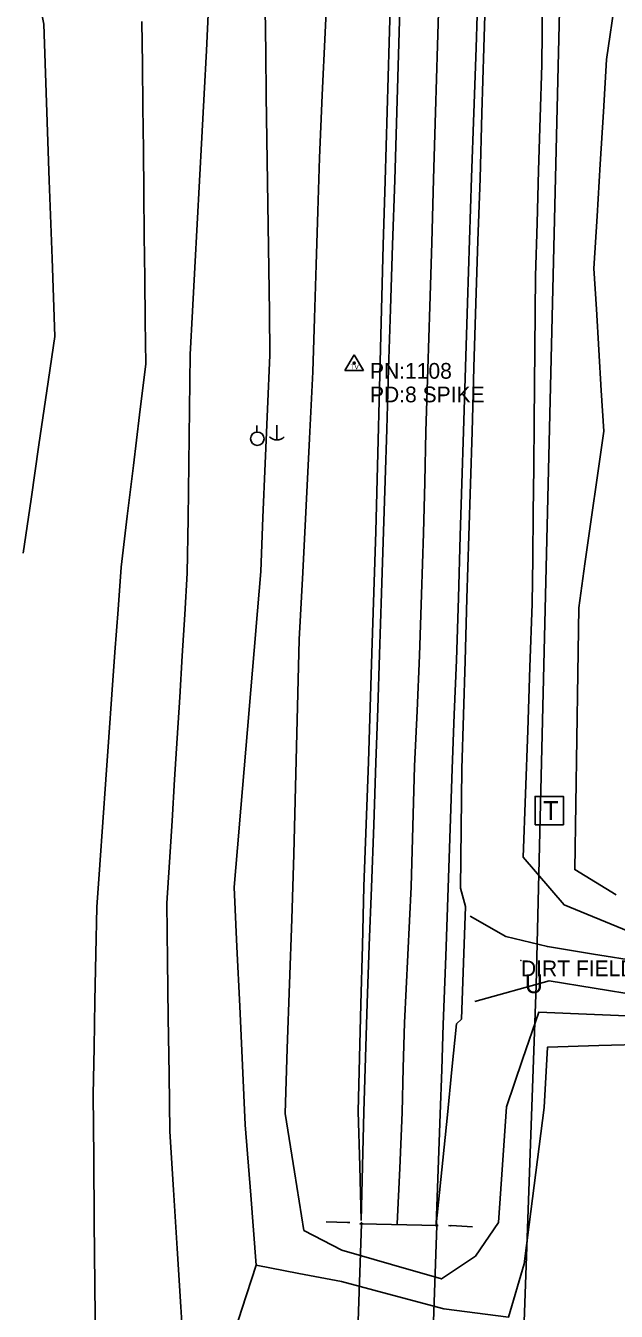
# Model space of a CAD drawing. Extents: x 1445297 to 1476720, y 2042269 to 2057889.
# Drawn here: x 1445978.9 to 1446166.6, y 2044126.9 to 2044535.6 of the extents above; entities that cross this region are included whole.
import ezdxf

# ---------------------------------------------------------------- set-up
doc = ezdxf.new("R2010")
doc.units = 0
for name, color, linetype in [('S_BRIDGE', 7, 'Continuous'), ('S_DITCHLINE', 7, 'Continuous'), ('S_DRIVEWAY', 7, 'Continuous'), ('S_EDGE_PAVEMENT', 7, 'Continuous'), ('S_MSC_PT_SYM', 7, 'Continuous'), ('S_PAVEMENT_CROWN', 7, 'Continuous'), ('S_SECONDARY_CTL', 7, 'Continuous'), ('S_SECONDARY_CTL_ANNOT', 7, 'Continuous'), ('S_SHOULDER', 7, 'Continuous'), ('S_STR_PT_SYM', 7, 'Continuous'), ('S_STREAM', 7, 'Continuous'), ('S_SURVEY_TEXT_ANNOT', 7, 'Continuous'), ('S_TELEPHONE_UTILITIES', 7, 'Continuous'), ('S_UNDERGROUND_CABLE', 7, 'Continuous'), ('S_UTILITY_POLE', 7, 'Continuous'), ('S_UTL_PT_SYM', 7, 'Continuous'), ('S_WALL', 7, 'Continuous')]:
    doc.layers.add(name, color=color, linetype=linetype)

msp = doc.modelspace()

# ---------------------------------------------------------------- linework, layer by layer
at = {"layer": 'S_BRIDGE'}
for p, q in [((1446083.17, 2044079.68), (1446085.63, 2044154.69)), ((1446085.63, 2044154.69), (1446109.56, 2044154.24)), ((1446109.56, 2044154.24), (1446107.11, 2044078.9))]:
    msp.add_line(p, q, dxfattribs=at)
at = {"layer": 'S_DITCHLINE'}
for points in [[(1445978.15, 2044367.9), (1445980.65, 2044385.13), (1445983.14, 2044402.36), (1445985.64, 2044419.58), (1445988.13, 2044436.81), (1445987.28, 2044461.63), (1445986.42, 2044486.45), (1445985.57, 2044511.27), (1445984.71, 2044536.09), (1445981.85, 2044550.56), (1445978.98, 2044565.02), (1445976.11, 2044579.49)], [(1446029.4, 2044109.71), (1446028.22, 2044128.31), (1446027.05, 2044146.91), (1446025.87, 2044165.51), (1446024.69, 2044184.11), (1446024.47, 2044202.24), (1446024.25, 2044220.37), (1446024.03, 2044238.5), (1446023.82, 2044256.64), (1446024.62, 2044269.75), (1446025.43, 2044282.86), (1446026.24, 2044295.98), (1446027.05, 2044309.09), (1446027.86, 2044322.2), (1446028.67, 2044335.32), (1446029.48, 2044348.43), (1446030.29, 2044361.54), (1446030.52, 2044378.93), (1446030.75, 2044396.32), (1446030.98, 2044413.72), (1446031.21, 2044431.11), (1446031.94, 2044444.91), (1446032.68, 2044458.72), (1446033.41, 2044472.52), (1446034.14, 2044486.32), (1446034.87, 2044500.13), (1446035.6, 2044513.93), (1446036.33, 2044527.74), (1446037.06, 2044541.54)], [(1446166.64, 2044259.28), (1446153.45, 2044267.34), (1446153.77, 2044288.14), (1446154.08, 2044308.94), (1446154.4, 2044329.74), (1446154.71, 2044350.54), (1446156.69, 2044364.58), (1446158.67, 2044378.62), (1446160.66, 2044392.66), (1446162.64, 2044406.7), (1446161.86, 2044419.64), (1446161.08, 2044432.58), (1446160.3, 2044445.52), (1446159.52, 2044458.46), (1446160.53, 2044475.06), (1446161.54, 2044491.67), (1446162.55, 2044508.27), (1446163.56, 2044524.88), (1446166.4, 2044544.53)], [(1446043.13, 2044113.76), (1446047.64, 2044127.65), (1446052.16, 2044141.54), (1446050.44, 2044163.85), (1446048.72, 2044186.16), (1446047.84, 2044205.05), (1446046.95, 2044223.94), (1446046.06, 2044242.83), (1446045.17, 2044261.72), (1446046.23, 2044274.27), (1446047.28, 2044286.83), (1446048.33, 2044299.38), (1446049.39, 2044311.93), (1446050.44, 2044324.48), (1446051.49, 2044337.03), (1446052.55, 2044349.58), (1446053.6, 2044362.14), (1446054.34, 2044379.32), (1446055.08, 2044396.5), (1446055.82, 2044413.68), (1446056.56, 2044430.86), (1446056.37, 2044444.61), (1446056.17, 2044458.36), (1446055.97, 2044472.11), (1446055.78, 2044485.86), (1446055.58, 2044499.61), (1446055.39, 2044513.36), (1446055.19, 2044527.11), (1446055, 2044540.86)], [(1446001.05, 2044115.1), (1446000.88, 2044135.29), (1446000.7, 2044155.49), (1446000.53, 2044175.68), (1446000.35, 2044195.87), (1446000.64, 2044210.75), (1446000.93, 2044225.63), (1446001.22, 2044240.52), (1446001.5, 2044255.4), (1446002.47, 2044268.91), (1446003.43, 2044282.43), (1446004.4, 2044295.94), (1446005.36, 2044309.46), (1446006.33, 2044322.98), (1446007.29, 2044336.49), (1446008.26, 2044350.01), (1446009.22, 2044363.52), (1446011.19, 2044379.67), (1446013.16, 2044395.82), (1446015.13, 2044411.97), (1446017.1, 2044428.12), (1446016.94, 2044441.72), (1446016.78, 2044455.33), (1446016.62, 2044468.94), (1446016.47, 2044482.54), (1446016.31, 2044496.15), (1446016.15, 2044509.75), (1446015.99, 2044523.36), (1446015.83, 2044536.97)], [(1446052.16, 2044141.54), (1446065.73, 2044138.95), (1446079.29, 2044136.37), (1446095.55, 2044132.02), (1446111.81, 2044127.68), (1446132.33, 2044125.05), (1446137.31, 2044142.04), (1446138.9, 2044154.47), (1446140.49, 2044166.89), (1446142.09, 2044179.31), (1446143.68, 2044191.74), (1446144.8, 2044210.94), (1446161.07, 2044211.42), (1446177.35, 2044211.9)]]:
    msp.add_lwpolyline(points, dxfattribs=at)
at = {"layer": 'S_DRIVEWAY'}
for points in [[(1446120.2, 2044252.54), (1446131.57, 2044246.1), (1446144.72, 2044242.87), (1446159.4, 2044240.47), (1446174.09, 2044238.08), (1446188.77, 2044235.68), (1446203.45, 2044233.29), (1446218.13, 2044230.89), (1446232.81, 2044228.5), (1446247.49, 2044226.1), (1446262.18, 2044223.71), (1446275.63, 2044222.1), (1446289.08, 2044220.5), (1446302.53, 2044218.89), (1446315.98, 2044217.29), (1446330.69, 2044216.84), (1446345.39, 2044216.38), (1446360.1, 2044215.93), (1446374.81, 2044215.47), (1446389.39, 2044215.28), (1446403.98, 2044215.08), (1446418.56, 2044214.89), (1446433.15, 2044214.69)], [(1446121.63, 2044225.44), (1446145.27, 2044231.95), (1446159.59, 2044229.64), (1446173.9, 2044227.34), (1446188.22, 2044225.04), (1446202.53, 2044222.73), (1446216.85, 2044220.43), (1446231.17, 2044218.12), (1446245.48, 2044215.82), (1446259.8, 2044213.52), (1446273.64, 2044211.76), (1446287.48, 2044209.99), (1446301.32, 2044208.23), (1446315.16, 2044206.47), (1446330.01, 2044206.17), (1446344.87, 2044205.87), (1446359.72, 2044205.56), (1446374.57, 2044205.26), (1446389.23, 2044205.3), (1446403.89, 2044205.33), (1446418.55, 2044205.37), (1446433.2, 2044205.41)]]:
    msp.add_lwpolyline(points, dxfattribs=at)
at = {"layer": 'S_EDGE_PAVEMENT'}
for points in [[(1446085.51, 2044155.74), (1446085.98, 2044173.03), (1446086.44, 2044190.32), (1446086.93, 2044207.59), (1446087.43, 2044224.85), (1446088.13, 2044243.27), (1446088.83, 2044261.7), (1446089.53, 2044281.54), (1446090.23, 2044301.38), (1446090.79, 2044318.55), (1446091.35, 2044335.73), (1446092.01, 2044355.26), (1446092.67, 2044374.79), (1446093.17, 2044391.06), (1446093.67, 2044407.32), (1446094.26, 2044426.43), (1446094.85, 2044445.54), (1446095.53, 2044466.02), (1446096.2, 2044486.51), (1446096.84, 2044508.28), (1446097.48, 2044530.06), (1446098.11, 2044551.51)], [(1446109.42, 2044154.37), (1446110.05, 2044171.97), (1446110.68, 2044189.57), (1446111.15, 2044203.84), (1446111.63, 2044218.12), (1446112.42, 2044239.83), (1446113.22, 2044261.54), (1446113.82, 2044280.46), (1446114.43, 2044299.37), (1446115.13, 2044316.67), (1446115.83, 2044333.97), (1446116.44, 2044353.74), (1446117.05, 2044373.51), (1446117.56, 2044390.05), (1446118.07, 2044406.6), (1446118.7, 2044427.06), (1446119.33, 2044447.53), (1446119.99, 2044467.43), (1446120.65, 2044487.33), (1446121.37, 2044507.97), (1446122.08, 2044528.6), (1446122.72, 2044549.46)], [(1446109.42, 2044154.37), (1446110.05, 2044171.97), (1446110.68, 2044189.57), (1446111.15, 2044203.84), (1446111.63, 2044218.12), (1446112.42, 2044239.83), (1446113.22, 2044261.54), (1446113.82, 2044280.46), (1446114.43, 2044299.37), (1446115.13, 2044316.67), (1446115.83, 2044333.97), (1446116.44, 2044353.74), (1446117.05, 2044373.51), (1446117.56, 2044390.05), (1446118.07, 2044406.6), (1446118.7, 2044427.06), (1446119.33, 2044447.53), (1446119.99, 2044467.43), (1446120.65, 2044487.33), (1446121.37, 2044507.97), (1446122.08, 2044528.6), (1446122.72, 2044549.46)]]:
    msp.add_lwpolyline(points, dxfattribs=at)
at = {"layer": 'S_MSC_PT_SYM'}
msp.add_lwpolyline([(1446136.33, 2044238.45), (1446136.33, 2044238.5), (1446136.33, 2044238.45), (1446136.28, 2044238.45), (1446136.33, 2044238.45), (1446136.33, 2044238.4), (1446136.33, 2044238.45), (1446136.38, 2044238.45)], dxfattribs=at)
at = {"layer": 'S_PAVEMENT_CROWN'}
msp.add_lwpolyline([(1446097.02, 2044154.77), (1446097.8, 2044172.46), (1446098.58, 2044190.14), (1446098.93, 2044204.37), (1446099.28, 2044218.6), (1446100.35, 2044240.22), (1446101.41, 2044261.85), (1446101.98, 2044281.03), (1446102.54, 2044300.21), (1446103.33, 2044317.79), (1446104.12, 2044335.37), (1446104.75, 2044354.85), (1446105.39, 2044374.32), (1446105.76, 2044390.47), (1446106.14, 2044406.62), (1446106.75, 2044426.48), (1446107.36, 2044446.34), (1446107.96, 2044466.62), (1446108.56, 2044486.89), (1446109.19, 2044508.14), (1446109.82, 2044529.39), (1446110.41, 2044550.33)], dxfattribs=at)
at = {"layer": 'S_SECONDARY_CTL'}
for p, q in [((1446083.35, 2044431.02), (1446080.34, 2044426.07)), ((1446083.35, 2044431.02), (1446086.3, 2044426.07)), ((1446080.34, 2044426.07), (1446086.3, 2044426.07))]:
    msp.add_line(p, q, dxfattribs=at)
for radius in [0.311, 0.183, 0.103]:
    msp.add_circle((1446083.35, 2044428.41), radius, dxfattribs=at)
at = {"layer": 'S_SHOULDER'}
for points in [[(1446092.03, 2044445.38), (1446092.58, 2044465.83), (1446093.12, 2044486.28), (1446093.79, 2044508.32), (1446094.45, 2044530.36), (1446095.05, 2044551.93), (1446095.64, 2044573.49), (1446096.34, 2044593.67), (1446097.03, 2044613.86), (1446097.67, 2044635.16), (1446098.31, 2044656.46), (1446099.01, 2044676.99), (1446099.71, 2044697.52), (1446100.23, 2044716.92), (1446100.74, 2044736.31), (1446101.24, 2044749.26), (1446101.75, 2044762.2), (1446101.73, 2044769.88)], [(1446109.42, 2044154.37), (1446111.22, 2044171.88), (1446113.02, 2044189.38), (1446114.41, 2044203.83), (1446115.8, 2044218.27), (1446117.4, 2044219.78), (1446118.05, 2044237.69), (1446118.71, 2044255.6), (1446117.15, 2044261.41), (1446117.32, 2044280.39), (1446117.49, 2044299.37), (1446118.07, 2044316.54), (1446118.64, 2044333.7), (1446119.18, 2044353.56), (1446119.72, 2044373.42), (1446120.25, 2044389.97), (1446120.78, 2044406.52), (1446121.4, 2044426.96), (1446122.02, 2044447.39), (1446122.67, 2044467.24), (1446123.32, 2044487.08), (1446123.94, 2044507.84), (1446124.56, 2044528.61), (1446125.18, 2044549.35)], [(1446109.42, 2044154.37), (1446111.22, 2044171.88), (1446113.02, 2044189.38), (1446114.41, 2044203.83), (1446115.8, 2044218.27), (1446117.4, 2044219.78), (1446118.05, 2044237.69), (1446118.71, 2044255.6), (1446117.15, 2044261.41), (1446117.32, 2044280.39), (1446117.49, 2044299.37), (1446118.07, 2044316.54), (1446118.64, 2044333.7), (1446119.18, 2044353.56), (1446119.72, 2044373.42), (1446120.25, 2044389.97), (1446120.78, 2044406.52), (1446121.4, 2044426.96), (1446122.02, 2044447.39), (1446122.67, 2044467.24), (1446123.32, 2044487.08), (1446123.94, 2044507.84), (1446124.56, 2044528.61), (1446125.18, 2044549.35)], [(1446090.24, 2044374.87), (1446092.03, 2044445.38)], [(1446085.51, 2044155.74), (1446085.08, 2044173.1), (1446084.64, 2044190.46), (1446085.06, 2044207.49), (1446085.48, 2044224.53), (1446085.93, 2044243.25), (1446086.38, 2044261.98), (1446087.14, 2044281.81), (1446087.89, 2044301.64), (1446088.42, 2044318.92), (1446088.94, 2044336.2), (1446089.59, 2044355.53), (1446090.24, 2044374.87), (1446090.24, 2044374.87)]]:
    msp.add_lwpolyline(points, dxfattribs=at)
at = {"layer": 'S_STR_PT_SYM'}
for points in [[(1446085.63, 2044154.69), (1446085.63, 2044155.19), (1446085.63, 2044154.69), (1446085.13, 2044154.69), (1446085.63, 2044154.69), (1446085.63, 2044154.19), (1446085.63, 2044154.69), (1446086.13, 2044154.69)], [(1446109.56, 2044154.24), (1446109.56, 2044154.74), (1446109.56, 2044154.24), (1446109.06, 2044154.24), (1446109.56, 2044154.24), (1446109.56, 2044153.74), (1446109.56, 2044154.24), (1446110.06, 2044154.24)]]:
    msp.add_lwpolyline(points, dxfattribs=at)
at = {"layer": 'S_STREAM'}
for points in [[(1446067.35, 2044152.66), (1446064.36, 2044171.25), (1446061.36, 2044189.84), (1446062.07, 2044210.44), (1446062.78, 2044231.04), (1446063.48, 2044251.64), (1446064.19, 2044272.24), (1446064.61, 2044289.31), (1446065.04, 2044306.38), (1446065.46, 2044323.46), (1446065.89, 2044340.53), (1446066.97, 2044361.8), (1446068.05, 2044383.08), (1446069.14, 2044404.36), (1446070.22, 2044425.63), (1446070.73, 2044442.64), (1446071.24, 2044459.64), (1446071.75, 2044476.65), (1446072.27, 2044493.65), (1446073.2, 2044513.58), (1446074.14, 2044533.5), (1446075.07, 2044553.43)], [(1446170.36, 2044247.78), (1446150.03, 2044256.1), (1446136.99, 2044271.26), (1446137.73, 2044291.4), (1446138.47, 2044311.55), (1446139.2, 2044331.69), (1446139.94, 2044351.84), (1446140.1, 2044366.31), (1446140.26, 2044380.79), (1446140.41, 2044395.27), (1446140.57, 2044409.74), (1446140.77, 2044432.91), (1446140.98, 2044456.09), (1446141.47, 2044472.86), (1446141.96, 2044489.63), (1446142.46, 2044506.41), (1446142.95, 2044523.18), (1446143.21, 2044543.98)], [(1446067.35, 2044152.66), (1446079.37, 2044146.37), (1446095.21, 2044141.8), (1446111.04, 2044137.24), (1446121.92, 2044144.5), (1446129.16, 2044155.12), (1446130.43, 2044173.5), (1446131.69, 2044191.88), (1446136.83, 2044206.94), (1446141.97, 2044222), (1446159.7, 2044221.3), (1446177.43, 2044220.59)]]:
    msp.add_lwpolyline(points, dxfattribs=at)
at = {"layer": 'S_TELEPHONE_UTILITIES'}
msp.add_lwpolyline([(1446140.83, 2044281.63), (1446140.83, 2044290.63), (1446149.83, 2044290.63), (1446149.83, 2044281.63)], close=True, dxfattribs=at)
at = {"layer": 'S_UNDERGROUND_CABLE'}
for p, q in [((1446154.27, 2044781.92), (1446141.2, 2044230.61)), ((1446141.2, 2044230.61), (1446119.29, 2043617.64))]:
    msp.add_line(p, q, dxfattribs=at)
at = {"layer": 'S_UTILITY_POLE'}
for p, q in [((1446052.4, 2044406.48), (1446052.4, 2044408.59)), ((1446058.71, 2044408.68), (1446058.71, 2044403.95))]:
    msp.add_line(p, q, dxfattribs=at)
msp.add_circle((1446052.53, 2044404.34), 2.13, dxfattribs=at)
msp.add_arc((1446058.77, 2044407.38), 3.41, 226.3972, 313.6028, dxfattribs=at)
at = {"layer": 'S_WALL'}
for points in [[(1446081.95, 2044155.1), (1446081.45, 2044155.1), (1446081.24, 2044155.13), (1446074.44, 2044155.36)], [(1446113.26, 2044154.25), (1446113.88, 2044154.14), (1446114.12, 2044154.16), (1446120.93, 2044153.74)]]:
    msp.add_lwpolyline(points, dxfattribs=at)

# ---------------------------------------------------------------- texts
at = {"layer": 'S_SECONDARY_CTL'}
msp.add_text('TV', height=1.5, dxfattribs=at).set_placement((1446082.15, 2044426.4))
at = {"layer": 'S_SECONDARY_CTL_ANNOT'}
for s, p in [('PN:1108', (1446088.35, 2044423.41)), ('PD:8 SPIKE', (1446088.35, 2044415.91))]:
    msp.add_text(s, height=5, dxfattribs=at).set_placement(p)
at = {"layer": 'S_SURVEY_TEXT_ANNOT'}
msp.add_text('DIRT FIELD ROAD', height=5, dxfattribs=at).set_placement((1446136.33, 2044233.45))
at = {"layer": 'S_TELEPHONE_UTILITIES'}
msp.add_text('T', height=6, dxfattribs=at).set_placement((1446143.4, 2044283.13))
at = {"layer": 'S_UTL_PT_SYM'}
msp.add_text('U', height=6, dxfattribs=at).set_placement((1446137.57, 2044228.06))

doc.saveas('drawing.dxf')
